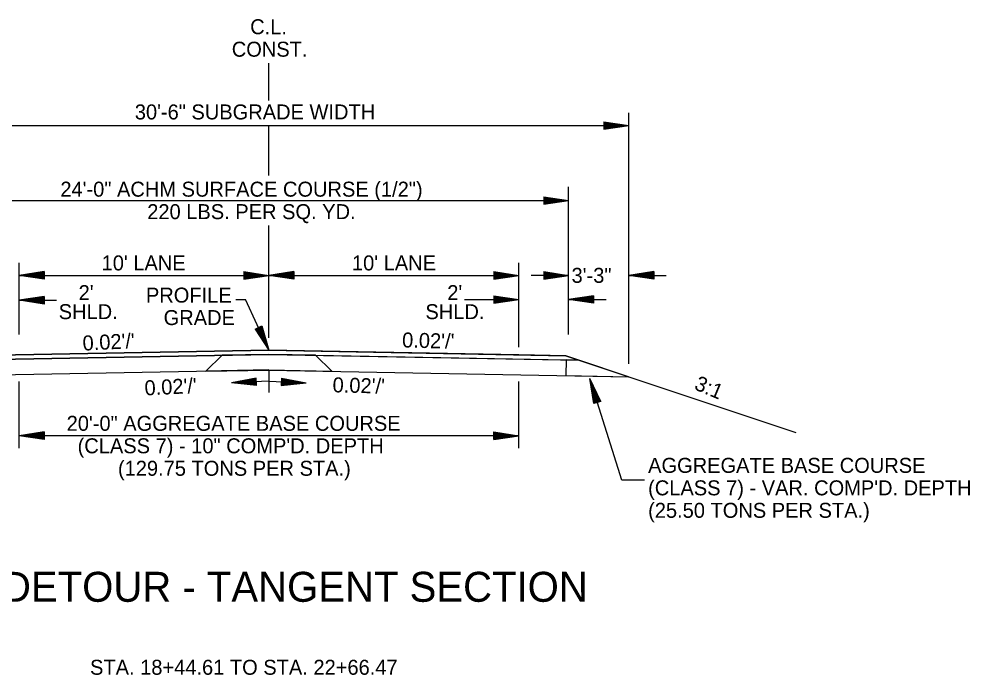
# Model space of a CAD drawing. Extents: x 138 to 3619, y -519 to 1449.
# Drawn here: x 2402.4 to 2783, y 692.2 to 954.8 of the extents above; entities that cross this region are included whole.
import ezdxf

# ---------------------------------------------------------------- set-up
doc = ezdxf.new("R2010")
doc.units = 0
for name, color, linetype in [('R_Annotation', 7, 'Continuous'), ('R_Centerline', 7, 'Continuous'), ('R_Dimension', 7, 'Continuous'), ('R_No Plot', 7, 'Continuous')]:
    doc.layers.add(name, color=color, linetype=linetype)

msp = doc.modelspace()

# ---------------------------------------------------------------- linework, layer by layer
at = {"layer": 'R_Annotation'}
for p, q in [((2502.36, 822.22), (2383.54, 820.01)), ((2502.36, 822.22), (2621.17, 820.01)), ((2502.36, 820.55), (2378.33, 818.27)), ((2502.36, 820.55), (2626.38, 818.27)), ((2621.17, 820.01), (2713.34, 789.28)), ((2502.36, 814.3), (2358.31, 811.6)), ((2502.36, 814.3), (2646.4, 811.6))]:
    msp.add_line(p, q, dxfattribs=at)
at = {"layer": 'R_Centerline'}
for p, q in [((2502.36, 922.22), (2502.36, 937.22)), ((2502.36, 892.22), (2502.36, 912.22)), ((2502.36, 827.22), (2502.36, 872.22))]:
    msp.add_line(p, q, dxfattribs=at)
at = {"layer": 'R_Dimension'}
for p, q in [((2636.4, 913.72), (2646.4, 912.22)), ((2636.4, 913.72), (2636.4, 910.72)), ((2646.4, 816.76), (2646.4, 917.22)), ((2359.92, 912.22), (2646.4, 912.22)), ((2636.4, 913.47), (2644.73, 912.22)), ((2636.4, 913.21), (2643.01, 912.22)), ((2636.4, 912.96), (2641.34, 912.22)), ((2636.4, 912.7), (2639.65, 912.22)), ((2636.4, 912.45), (2637.98, 912.22)), ((2636.4, 910.72), (2646.4, 912.22)), ((2636.4, 911.73), (2639.65, 912.22)), ((2636.4, 911.22), (2643.01, 912.22)), ((2636.4, 910.97), (2644.73, 912.22)), ((2636.4, 911.47), (2641.34, 912.22)), ((2636.4, 911.98), (2637.98, 912.22)), ((2622.36, 828.56), (2622.36, 887.72)), ((2612.36, 883.72), (2622.36, 882.22)), ((2612.36, 883.72), (2612.36, 880.72)), ((2612.36, 883.47), (2620.69, 882.22)), ((2612.36, 883.22), (2618.97, 882.22)), ((2382.37, 882.23), (2622.36, 882.23)), ((2612.36, 882.97), (2617.3, 882.22)), ((2612.36, 882.71), (2615.61, 882.22)), ((2612.36, 882.46), (2613.94, 882.22)), ((2612.36, 880.72), (2622.36, 882.22)), ((2612.36, 881.73), (2615.61, 882.22)), ((2612.36, 881.23), (2618.97, 882.22)), ((2612.36, 880.97), (2620.69, 882.22)), ((2612.36, 881.48), (2617.3, 882.22)), ((2612.36, 881.99), (2613.94, 882.22)), ((2402.37, 828.57), (2402.37, 857.22)), ((2602.36, 823.5), (2602.36, 857.22)), ((2412.37, 853.72), (2402.37, 852.22)), ((2412.37, 853.47), (2404.04, 852.22)), ((2412.37, 853.21), (2405.76, 852.22)), ((2412.37, 852.96), (2407.42, 852.22)), ((2412.37, 852.7), (2409.12, 852.22)), ((2412.37, 853.72), (2412.37, 850.72)), ((2492.36, 853.72), (2502.36, 852.22)), ((2492.36, 853.72), (2492.36, 850.72)), ((2492.36, 853.47), (2500.69, 852.22)), ((2492.36, 853.21), (2498.97, 852.22)), ((2492.36, 852.96), (2497.3, 852.22)), ((2492.36, 852.7), (2495.61, 852.22)), ((2512.36, 853.72), (2502.36, 852.22)), ((2512.36, 853.47), (2504.03, 852.22)), ((2512.36, 853.21), (2505.75, 852.22)), ((2512.36, 852.96), (2507.41, 852.22)), ((2512.36, 852.7), (2509.11, 852.22)), ((2512.36, 853.72), (2512.36, 850.72)), ((2592.36, 853.72), (2602.36, 852.22)), ((2592.36, 853.72), (2592.36, 850.72)), ((2592.36, 853.47), (2600.69, 852.22)), ((2592.36, 853.21), (2598.97, 852.22)), ((2592.36, 852.96), (2597.3, 852.22)), ((2592.36, 852.7), (2595.61, 852.22)), ((2612.36, 853.72), (2622.36, 852.22)), ((2612.36, 853.72), (2612.36, 850.72)), ((2612.36, 853.47), (2620.69, 852.22)), ((2612.36, 853.21), (2618.97, 852.22)), ((2612.36, 852.96), (2617.3, 852.22)), ((2612.36, 852.7), (2615.61, 852.22)), ((2656.4, 853.72), (2646.4, 852.22)), ((2656.4, 853.47), (2648.07, 852.22)), ((2656.4, 853.21), (2649.79, 852.22)), ((2656.4, 852.96), (2651.45, 852.22)), ((2656.4, 852.7), (2653.15, 852.22)), ((2656.4, 853.72), (2656.4, 850.72)), ((2402.37, 852.22), (2602.36, 852.22)), ((2412.37, 850.72), (2402.37, 852.22)), ((2412.37, 850.97), (2404.04, 852.22)), ((2412.37, 851.22), (2405.76, 852.22)), ((2412.37, 851.47), (2407.42, 852.22)), ((2412.37, 851.73), (2409.12, 852.22)), ((2412.37, 852.45), (2410.79, 852.22)), ((2412.37, 851.98), (2410.79, 852.22)), ((2492.36, 852.45), (2493.94, 852.22)), ((2492.36, 850.72), (2502.36, 852.22)), ((2492.36, 851.73), (2495.61, 852.22)), ((2492.36, 851.22), (2498.97, 852.22)), ((2492.36, 850.97), (2500.69, 852.22)), ((2492.36, 851.47), (2497.3, 852.22)), ((2492.36, 851.98), (2493.94, 852.22)), ((2512.36, 850.72), (2502.36, 852.22)), ((2512.36, 850.97), (2504.03, 852.22)), ((2512.36, 851.22), (2505.75, 852.22)), ((2512.36, 851.47), (2507.41, 852.22)), ((2512.36, 851.73), (2509.11, 852.22)), ((2512.36, 852.45), (2510.78, 852.22)), ((2512.36, 851.98), (2510.78, 852.22)), ((2592.36, 852.45), (2593.94, 852.22)), ((2592.36, 850.72), (2602.36, 852.22)), ((2592.36, 851.73), (2595.61, 852.22)), ((2592.36, 851.22), (2598.97, 852.22)), ((2592.36, 850.97), (2600.69, 852.22)), ((2592.36, 851.47), (2597.3, 852.22)), ((2592.36, 851.98), (2593.94, 852.22)), ((2622.36, 852.22), (2607.36, 852.22)), ((2612.36, 852.45), (2613.94, 852.22)), ((2612.36, 850.72), (2622.36, 852.22)), ((2612.36, 851.73), (2615.61, 852.22)), ((2612.36, 851.22), (2618.97, 852.22)), ((2612.36, 850.97), (2620.69, 852.22)), ((2612.36, 851.47), (2617.3, 852.22)), ((2612.36, 851.98), (2613.94, 852.22)), ((2646.4, 852.22), (2661.4, 852.22)), ((2656.4, 850.72), (2646.4, 852.22)), ((2656.4, 850.97), (2648.07, 852.22)), ((2656.4, 851.22), (2649.79, 852.22)), ((2656.4, 851.47), (2651.45, 852.22)), ((2656.4, 851.73), (2653.15, 852.22)), ((2656.4, 852.45), (2654.82, 852.22)), ((2656.4, 851.98), (2654.82, 852.22)), ((2412.37, 843.72), (2402.37, 842.22)), ((2412.37, 840.72), (2402.37, 842.22)), ((2402.37, 842.22), (2417.37, 842.22)), ((2412.37, 843.47), (2404.04, 842.22)), ((2412.37, 840.97), (2404.04, 842.22)), ((2412.37, 843.21), (2405.76, 842.22)), ((2412.37, 841.22), (2405.76, 842.22)), ((2412.37, 842.96), (2407.42, 842.22)), ((2412.37, 841.47), (2407.42, 842.22)), ((2412.37, 842.7), (2409.12, 842.22)), ((2412.37, 841.73), (2409.12, 842.22)), ((2412.37, 842.45), (2410.79, 842.22)), ((2412.37, 841.98), (2410.79, 842.22)), ((2412.37, 843.72), (2412.37, 840.72)), ((2489.12, 842.55), (2493.08, 842.55)), ((2580.62, 842.55), (2602.36, 842.55)), ((2592.36, 844.05), (2602.36, 842.55)), ((2592.36, 844.05), (2592.36, 841.05)), ((2592.36, 843.8), (2600.69, 842.55)), ((2592.36, 843.55), (2598.97, 842.55)), ((2592.36, 843.3), (2597.3, 842.55)), ((2592.36, 843.04), (2595.61, 842.55)), ((2592.36, 842.79), (2593.94, 842.55)), ((2592.36, 841.05), (2602.36, 842.55)), ((2592.36, 842.06), (2595.61, 842.55)), ((2592.36, 841.56), (2598.97, 842.55)), ((2592.36, 841.3), (2600.69, 842.55)), ((2592.36, 841.81), (2597.3, 842.55)), ((2592.36, 842.32), (2593.94, 842.55)), ((2632.36, 844.05), (2622.36, 842.55)), ((2632.36, 841.05), (2622.36, 842.55)), ((2622.36, 842.55), (2637.36, 842.55)), ((2632.36, 843.8), (2624.03, 842.55)), ((2632.36, 841.3), (2624.03, 842.55)), ((2632.36, 843.55), (2625.75, 842.55)), ((2632.36, 841.56), (2625.75, 842.55)), ((2632.36, 843.3), (2627.41, 842.55)), ((2632.36, 841.81), (2627.41, 842.55)), ((2632.36, 843.04), (2629.11, 842.55)), ((2632.36, 842.06), (2629.11, 842.55)), ((2632.36, 842.79), (2630.78, 842.55)), ((2632.36, 842.32), (2630.78, 842.55)), ((2632.36, 844.05), (2632.36, 841.05)), ((2496.84, 830.69), (2499.57, 831.94)), ((2496.84, 830.69), (2502.36, 822.22)), ((2497.07, 830.79), (2501.66, 823.74)), ((2497.3, 830.9), (2500.95, 825.3)), ((2497.52, 831), (2500.26, 826.82)), ((2497.76, 831.11), (2499.55, 828.36)), ((2497.99, 831.22), (2498.86, 829.88)), ((2498.42, 831.41), (2498.86, 829.88)), ((2498.65, 831.52), (2499.55, 828.36)), ((2498.88, 831.62), (2500.26, 826.82)), ((2499.11, 831.73), (2500.95, 825.3)), ((2499.34, 831.83), (2501.66, 823.74)), ((2499.57, 831.94), (2502.36, 822.22)), ((2383.54, 820.01), (2502.36, 822.22)), ((2502.36, 822.22), (2383.54, 820.01)), ((2621.17, 820.01), (2502.36, 822.22)), ((2502.36, 822.22), (2502.36, 822.22)), ((2502.36, 822.22), (2502.36, 822.22)), ((2621.17, 820.01), (2502.36, 822.22)), ((2502.36, 820.55), (2378.33, 818.27)), ((2378.33, 818.27), (2502.36, 820.55)), ((2477.13, 813.82), (2483.65, 820.21)), ((2483.65, 820.21), (2477.13, 813.82)), ((2483.65, 820.21), (2502.35, 820.58)), ((2502.35, 820.58), (2502.36, 820.58)), ((2521.06, 820.21), (2502.36, 820.58)), ((2502.36, 820.58), (2502.36, 820.58)), ((2502.36, 820.55), (2502.36, 820.55)), ((2502.36, 820.55), (2626.38, 818.27)), ((2502.36, 820.55), (2502.36, 820.55)), ((2502.36, 820.55), (2626.38, 818.27)), ((2527.58, 813.82), (2521.06, 820.21)), ((2527.58, 813.82), (2521.06, 820.21)), ((2626.38, 818.27), (2621.17, 820.01)), ((2626.38, 818.27), (2621.17, 820.01)), ((2621.33, 818.38), (2621.27, 812.07)), ((2626.38, 818.27), (2621.33, 818.38)), ((2646.35, 811.61), (2626.38, 818.27)), ((2502.35, 814.33), (2477.13, 813.82)), ((2497.3, 811.1), (2487.37, 809.21)), ((2497.31, 810.85), (2489.04, 809.27)), ((2497.42, 808.11), (2497.3, 811.1)), ((2502.36, 814.33), (2502.35, 814.33)), ((2502.36, 814.33), (2502.36, 814.33)), ((2502.36, 814.33), (2527.58, 813.82)), ((2502.36, 814.3), (2502.36, 805.31)), ((2507.41, 811.11), (2507.29, 808.11)), ((2507.4, 810.86), (2515.67, 809.27)), ((2507.41, 811.11), (2517.34, 809.21)), ((2621.27, 812.07), (2646.35, 811.61)), ((2635.29, 801.76), (2630.9, 810.87)), ((2632.43, 800.87), (2630.9, 810.87)), ((2402.37, 783.01), (2402.37, 809.72)), ((2502.36, 809.81), (2487.37, 809.21)), ((2497.42, 808.11), (2487.37, 809.21)), ((2497.41, 808.36), (2489.04, 809.27)), ((2497.32, 810.6), (2490.75, 809.34)), ((2497.4, 808.61), (2490.75, 809.34)), ((2497.33, 810.35), (2492.42, 809.41)), ((2497.39, 808.86), (2492.42, 809.41)), ((2497.34, 810.1), (2494.11, 809.48)), ((2497.38, 809.12), (2494.11, 809.48)), ((2497.35, 809.84), (2495.78, 809.54)), ((2497.37, 809.37), (2495.78, 809.54)), ((2502.36, 809.81), (2517.34, 809.21)), ((2507.29, 808.11), (2517.34, 809.21)), ((2507.3, 808.36), (2515.67, 809.27)), ((2507.31, 808.61), (2513.95, 809.34)), ((2507.32, 808.86), (2512.29, 809.41)), ((2507.33, 809.12), (2510.6, 809.48)), ((2507.34, 809.37), (2508.93, 809.54)), ((2507.36, 809.84), (2508.93, 809.54)), ((2507.37, 810.09), (2510.6, 809.48)), ((2507.38, 810.35), (2512.29, 809.41)), ((2507.39, 810.6), (2513.95, 809.34)), ((2602.36, 783.01), (2602.36, 809.72)), ((2635.05, 801.69), (2631.4, 809.28)), ((2632.66, 800.95), (2631.4, 809.28)), ((2632.91, 801.02), (2631.91, 807.63)), ((2634.81, 801.61), (2631.91, 807.63)), ((2634.57, 801.54), (2632.4, 806.04)), ((2633.15, 801.1), (2632.4, 806.04)), ((2633.39, 801.17), (2632.9, 804.42)), ((2634.32, 801.46), (2632.9, 804.42)), ((2635.29, 801.76), (2632.43, 800.87)), ((2633.63, 801.25), (2633.39, 802.83)), ((2634.08, 801.39), (2633.39, 802.83)), ((2412.37, 789.51), (2402.37, 788.01)), ((2602.36, 788.01), (2402.37, 788.01)), ((2412.37, 786.51), (2402.37, 788.01)), ((2412.37, 789.26), (2404.04, 788.01)), ((2412.37, 786.76), (2404.04, 788.01)), ((2412.37, 789), (2405.76, 788.01)), ((2412.37, 787.01), (2405.76, 788.01)), ((2412.37, 788.75), (2407.42, 788.01)), ((2412.37, 787.26), (2407.42, 788.01)), ((2412.37, 788.49), (2409.12, 788.01)), ((2412.37, 787.52), (2409.12, 788.01)), ((2412.37, 788.24), (2410.79, 788.01)), ((2412.37, 787.77), (2410.79, 788.01)), ((2412.37, 789.51), (2412.37, 786.51)), ((2592.36, 789.51), (2602.36, 788.01)), ((2592.36, 786.51), (2592.36, 789.51)), ((2592.36, 789.26), (2600.69, 788.01)), ((2592.36, 789), (2598.97, 788.01)), ((2592.36, 788.75), (2597.3, 788.01)), ((2592.36, 788.5), (2595.61, 788.01)), ((2592.36, 788.24), (2593.94, 788.01)), ((2592.36, 786.51), (2602.36, 788.01)), ((2592.36, 787.52), (2595.61, 788.01)), ((2592.36, 787.01), (2598.97, 788.01)), ((2592.36, 786.76), (2600.69, 788.01)), ((2592.36, 787.26), (2597.3, 788.01)), ((2592.36, 787.77), (2593.94, 788.01))]:
    msp.add_line(p, q, dxfattribs=at)
for points in [[(2502.36, 822.22), (2493.08, 842.55)], [(2521.06, 820.21), (2502.36, 820.58), (2483.65, 820.21)], [(2477.13, 813.82), (2502.36, 814.3), (2527.58, 813.82)], [(2652.66, 770.16), (2643.67, 770.16), (2630.9, 810.87)]]:
    msp.add_lwpolyline(points, dxfattribs=at)
at = {"layer": 'R_No Plot'}
for p, q in [((2502.36, 822.22), (2383.54, 820.01)), ((2602.35, 820.36), (2502.36, 822.22)), ((2383.38, 818.36), (2483.65, 820.21)), ((2483.65, 820.21), (2502.36, 820.58)), ((2483.65, 820.21), (2483.65, 820.21)), ((2502.36, 820.58), (2521.06, 820.21)), ((2521.06, 820.21), (2521.06, 820.21)), ((2521.06, 820.21), (2621.33, 818.36)), ((2602.36, 820.36), (2602.33, 820.33)), ((2602.33, 820.33), (2602.35, 820.36)), ((2621.17, 820.01), (2602.36, 820.36)), ((2626.38, 818.27), (2621.17, 820.01)), ((2621.33, 818.36), (2621.33, 818.38)), ((2621.33, 818.38), (2626.38, 818.27))]:
    msp.add_line(p, q, dxfattribs=at)

# ---------------------------------------------------------------- texts
at = {"layer": 'R_Annotation'}
for s, height, p in [('C.L.', 6, (2494.89, 948.76)), ('CONST.', 6, (2487.52, 939.76)), ('30\'-6" SUBGRADE WIDTH', 6, (2448.71, 914.64)), ('24\'-0" ACHM SURFACE COURSE (1/2")', 6, (2418.92, 883.72)), ('220 LBS. PER SQ. YD. ', 6, (2453.69, 874.72)), ("10' LANE", 6, (2435.43, 854.19)), ("10' LANE", 6, (2535.63, 854.19)), ('3\'-3"', 6, (2623.52, 849.22)), ("2'", 6, (2426.22, 842.3)), ('PROFILE', 6, (2453.16, 841.31)), ("2'", 6, (2573.77, 842.3)), ('SHLD.', 6, (2418.24, 834.68)), ('GRADE', 6, (2460.25, 832.31)), ('SHLD.', 6, (2565.03, 834.68)), ('20\'-0" AGGREGATE BASE COURSE', 6, (2421.43, 789.97)), ('(CLASS 7) - 10" COMP\'D. DEPTH', 6, (2425.82, 780.97)), ('(129.75 TONS PER STA.)', 6, (2441.97, 771.97)), ('AGGREGATE BASE COURSE', 6, (2654.16, 773.14)), ("(CLASS 7) - VAR. COMP'D. DEPTH", 6, (2654.16, 764.14)), ('(25.50 TONS PER STA.)', 6, (2654.16, 755.14)), ('TEMP. DETOUR - TANGENT SECTION', 12, (2342.06, 721.52)), ('STA. 18+44.61 TO STA. 22+66.47', 6, (2430.79, 692.3))]:
    msp.add_text(s, height=height, dxfattribs=at).set_placement(p)
for s, rotation, p in [("0.02'/'", 2.7804, (2427.95, 822.07)), ("0.02'/'", 358.3978, (2555.64, 823.39)), ("0.02'/'", 2.7804, (2452.75, 804.12)), ("0.02'/'", 358.3978, (2527.81, 805.43)), ('3:1', 337.2473, (2672.26, 806.72))]:
    msp.add_text(s, height=6, rotation=rotation, dxfattribs=at).set_placement(p)

doc.saveas('drawing.dxf')
